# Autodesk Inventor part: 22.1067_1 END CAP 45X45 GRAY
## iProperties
Created: 2007-01
Part Number: 22.1067_1 END CAP 45X45 GRAY
Document SubType Name: Modeling
Designer: Andy Moles
Material: ABS Plastic
Mass: 6.34649 g
Surface Area: 44.6715 cm^2
Volume: 5.98725 cm^3
Density: 1.06 g/cm^3
Author: Andy Moles
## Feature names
1. Extrusion1
2. Fillet1
3. Fillet2
4. Extrusion2
5. Fillet3
6. Mirror1
7. Mirror2
